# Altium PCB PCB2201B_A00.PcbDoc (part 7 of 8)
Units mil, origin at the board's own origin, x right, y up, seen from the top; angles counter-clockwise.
Board outline 4523.63 x 2358.23 mil, 6 copper layers (Top Layer, Signal Layer 2, Signal Layer 3, Signal Layer 4, Signal Layer 5, Bottom Layer), stack 61.221 mil thick; 383 components, 308 nets, 1386 pads, 1147 vias.
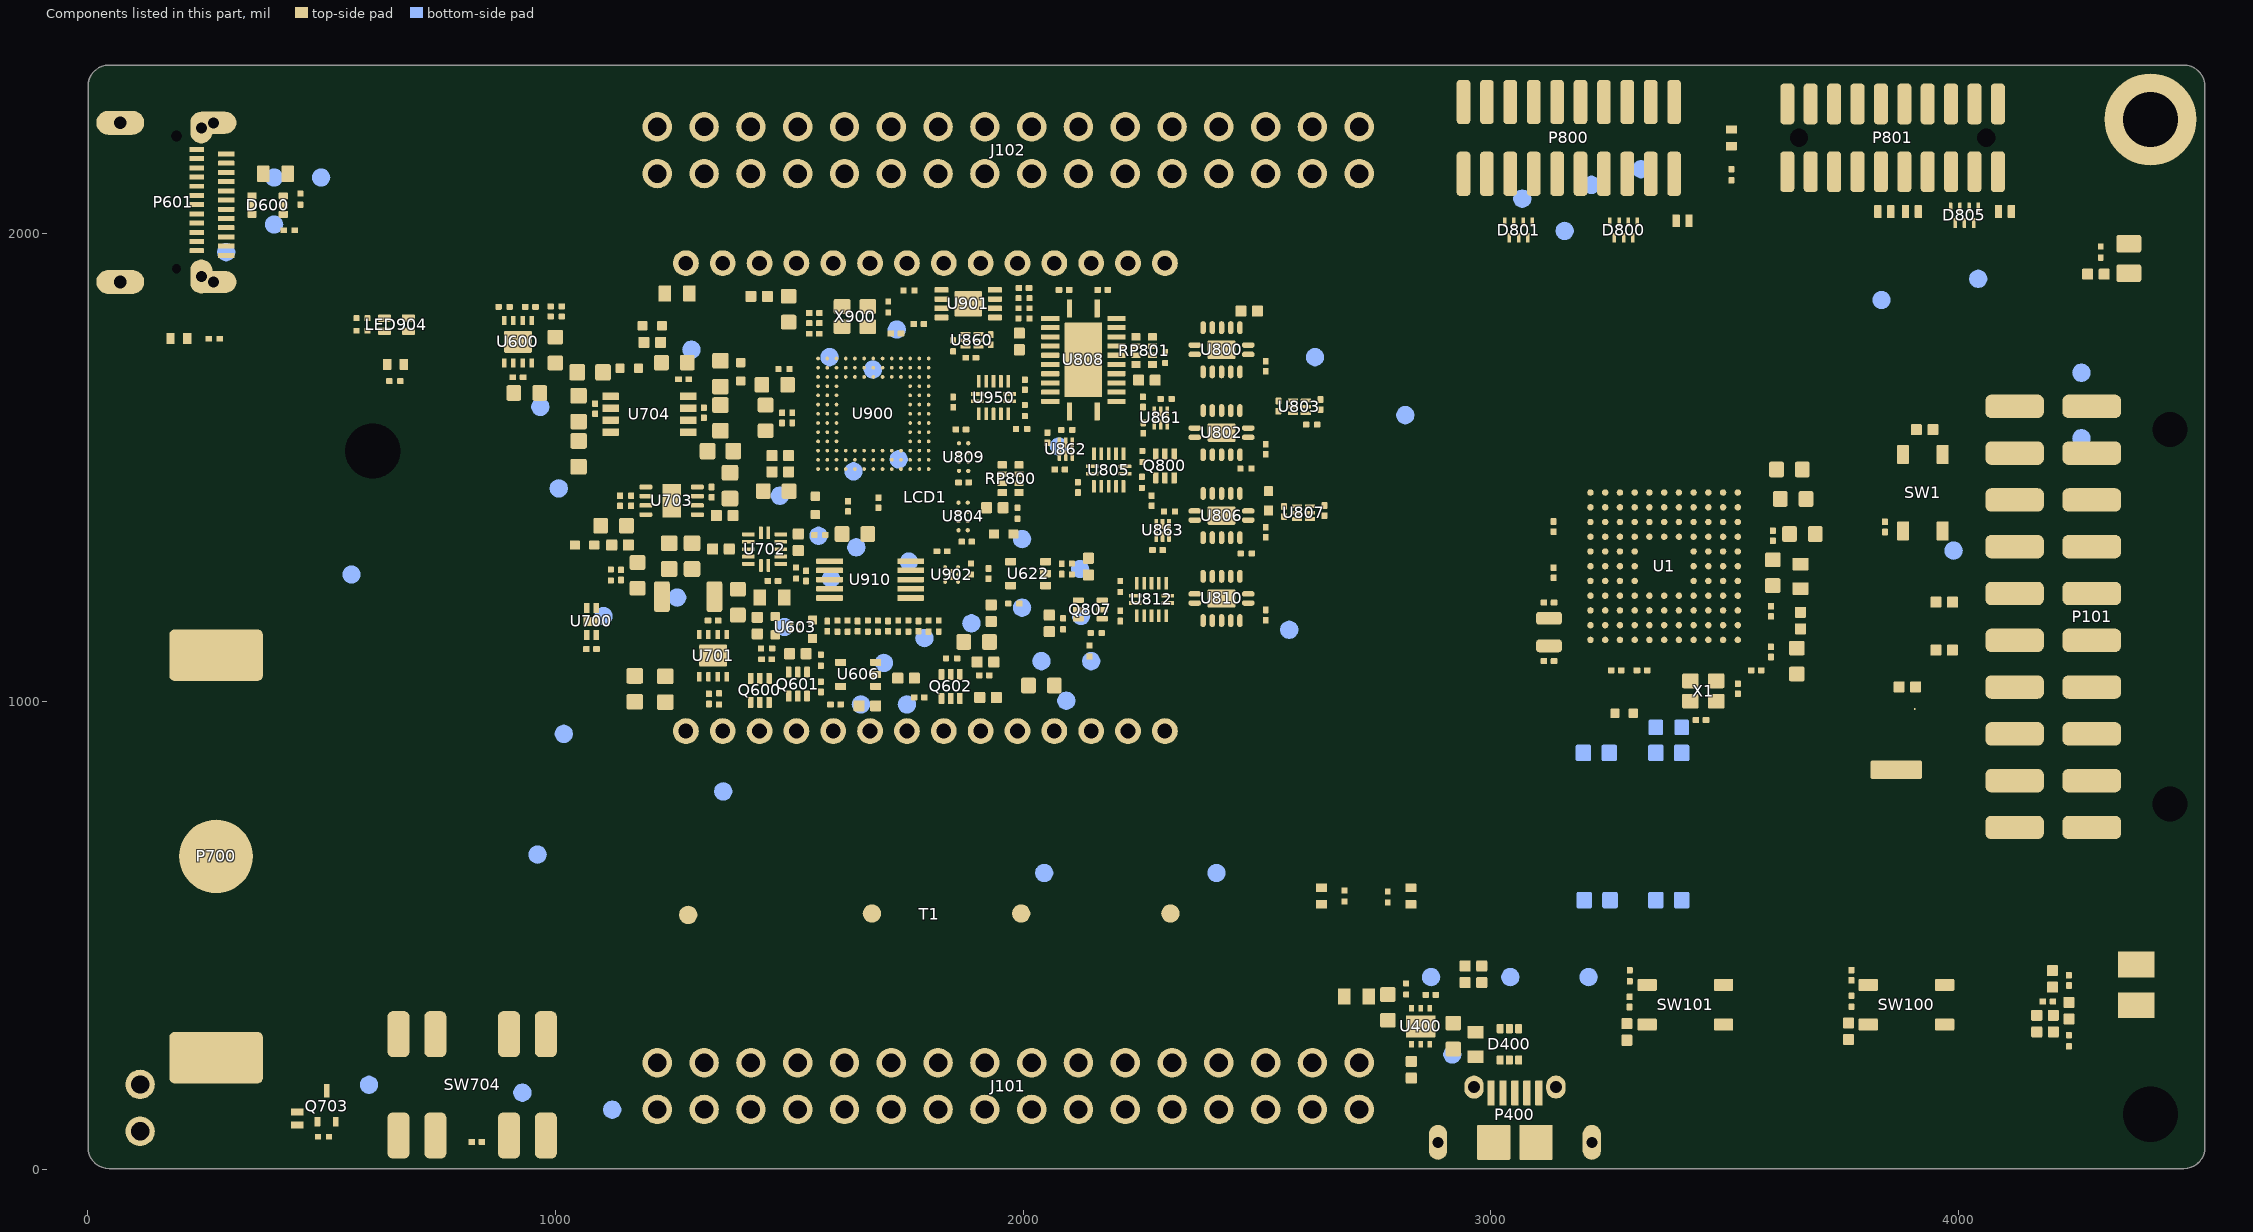
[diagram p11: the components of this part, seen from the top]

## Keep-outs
Bottom Layer:
  region: 2687,2128.47 ccw(c2718.5,2128.47) 2718.5,2096.98 ccw(c2718.5,2128.47) 2749.99,2128.47 ccw(c2718.5,2128.47) 2718.5,2159.97 ccw(c2718.5,2128.47)
  region: 2587,2128.47 ccw(c2618.5,2128.47) 2618.5,2096.98 ccw(c2618.5,2128.47) 2649.99,2128.47 ccw(c2618.5,2128.47) 2618.5,2159.97 ccw(c2618.5,2128.47)
  region: 1687,2128.47 ccw(c1718.5,2128.47) 1718.5,2096.98 ccw(c1718.5,2128.47) 1749.99,2128.47 ccw(c1718.5,2128.47) 1718.5,2159.97 ccw(c1718.5,2128.47)
  region: 1587,2128.47 ccw(c1618.5,2128.47) 1618.5,2096.98 ccw(c1618.5,2128.47) 1649.99,2128.47 ccw(c1618.5,2128.47) 1618.5,2159.97 ccw(c1618.5,2128.47)
  region: 1487,2128.47 ccw(c1518.5,2128.47) 1518.5,2096.98 ccw(c1518.5,2128.47) 1549.99,2128.47 ccw(c1518.5,2128.47) 1518.5,2159.97 ccw(c1518.5,2128.47)
  region: 1387,2128.47 ccw(c1418.5,2128.47) 1418.5,2096.98 ccw(c1418.5,2128.47) 1449.99,2128.47 ccw(c1418.5,2128.47) 1418.5,2159.97 ccw(c1418.5,2128.47)
  region: 1287,2128.47 ccw(c1318.5,2128.47) 1318.5,2096.98 ccw(c1318.5,2128.47) 1349.99,2128.47 ccw(c1318.5,2128.47) 1318.5,2159.97 ccw(c1318.5,2128.47)
  region: 2687,2228.47 ccw(c2718.5,2228.47) 2718.5,2196.98 ccw(c2718.5,2228.47) 2749.99,2228.47 ccw(c2718.5,2228.47) 2718.5,2259.97 ccw(c2718.5,2228.47)
  region: 2587,2228.47 ccw(c2618.5,2228.47) 2618.5,2196.98 ccw(c2618.5,2228.47) 2649.99,2228.47 ccw(c2618.5,2228.47) 2618.5,2259.97 ccw(c2618.5,2228.47)
  region: 2487,2228.47 ccw(c2518.5,2228.47) 2518.5,2196.98 ccw(c2518.5,2228.47) 2549.99,2228.47 ccw(c2518.5,2228.47) 2518.5,2259.97 ccw(c2518.5,2228.47)
  region: 2387,2228.47 ccw(c2418.5,2228.47) 2418.5,2196.98 ccw(c2418.5,2228.47) 2449.99,2228.47 ccw(c2418.5,2228.47) 2418.5,2259.97 ccw(c2418.5,2228.47)
  region: 2287,2228.47 ccw(c2318.5,2228.47) 2318.5,2196.98 ccw(c2318.5,2228.47) 2349.99,2228.47 ccw(c2318.5,2228.47) 2318.5,2259.97 ccw(c2318.5,2228.47)
  region: 2087,2228.47 ccw(c2118.5,2228.47) 2118.5,2196.98 ccw(c2118.5,2228.47) 2149.99,2228.47 ccw(c2118.5,2228.47) 2118.5,2259.97 ccw(c2118.5,2228.47)
  region: 1987,2228.47 ccw(c2018.5,2228.47) 2018.5,2196.98 ccw(c2018.5,2228.47) 2049.99,2228.47 ccw(c2018.5,2228.47) 2018.5,2259.97 ccw(c2018.5,2228.47)
  region: 1887,2228.47 ccw(c1918.5,2228.47) 1918.5,2196.98 ccw(c1918.5,2228.47) 1949.99,2228.47 ccw(c1918.5,2228.47) 1918.5,2259.97 ccw(c1918.5,2228.47)
  region: 1787,2228.47 ccw(c1818.5,2228.47) 1818.5,2196.98 ccw(c1818.5,2228.47) 1849.99,2228.47 ccw(c1818.5,2228.47) 1818.5,2259.97 ccw(c1818.5,2228.47)
  region: 1687,2228.47 ccw(c1718.5,2228.47) 1718.5,2196.98 ccw(c1718.5,2228.47) 1749.99,2228.47 ccw(c1718.5,2228.47) 1718.5,2259.97 ccw(c1718.5,2228.47)
  region: 1587,2228.47 ccw(c1618.5,2228.47) 1618.5,2196.98 ccw(c1618.5,2228.47) 1649.99,2228.47 ccw(c1618.5,2228.47) 1618.5,2259.97 ccw(c1618.5,2228.47)
  region: 1487,2228.47 ccw(c1518.5,2228.47) 1518.5,2196.98 ccw(c1518.5,2228.47) 1549.99,2228.47 ccw(c1518.5,2228.47) 1518.5,2259.97 ccw(c1518.5,2228.47)
  region: 1387,2228.47 ccw(c1418.5,2228.47) 1418.5,2196.98 ccw(c1418.5,2228.47) 1449.99,2228.47 ccw(c1418.5,2228.47) 1418.5,2259.97 ccw(c1418.5,2228.47)
  region: 1287,2228.47 ccw(c1318.5,2228.47) 1318.5,2196.98 ccw(c1318.5,2228.47) 1349.99,2228.47 ccw(c1318.5,2228.47) 1318.5,2259.97 ccw(c1318.5,2228.47)
  region: 2687,128.47 ccw(c2718.5,128.47) 2718.5,96.98 ccw(c2718.5,128.47) 2749.99,128.47 ccw(c2718.5,128.47) 2718.5,159.97 ccw(c2718.5,128.47)
  region: 2587,128.47 ccw(c2618.5,128.47) 2618.5,96.98 ccw(c2618.5,128.47) 2649.99,128.47 ccw(c2618.5,128.47) 2618.5,159.97 ccw(c2618.5,128.47)
  region: 2487,128.47 ccw(c2518.5,128.47) 2518.5,96.98 ccw(c2518.5,128.47) 2549.99,128.47 ccw(c2518.5,128.47) 2518.5,159.97 ccw(c2518.5,128.47)
  region: 2387,128.47 ccw(c2418.5,128.47) 2418.5,96.98 ccw(c2418.5,128.47) 2449.99,128.47 ccw(c2418.5,128.47) 2418.5,159.97 ccw(c2418.5,128.47)
  region: 2287,128.47 ccw(c2318.5,128.47) 2318.5,96.98 ccw(c2318.5,128.47) 2349.99,128.47 ccw(c2318.5,128.47) 2318.5,159.97 ccw(c2318.5,128.47)
  region: 2187,128.47 ccw(c2218.5,128.47) 2218.5,96.98 ccw(c2218.5,128.47) 2249.99,128.47 ccw(c2218.5,128.47) 2218.5,159.97 ccw(c2218.5,128.47)
  region: 2087,128.47 ccw(c2118.5,128.47) 2118.5,96.98 ccw(c2118.5,128.47) 2149.99,128.47 ccw(c2118.5,128.47) 2118.5,159.97 ccw(c2118.5,128.47)
  region: 1987,128.47 ccw(c2018.5,128.47) 2018.5,96.98 ccw(c2018.5,128.47) 2049.99,128.47 ccw(c2018.5,128.47) 2018.5,159.97 ccw(c2018.5,128.47)
  region: 1887,128.47 ccw(c1918.5,128.47) 1918.5,96.98 ccw(c1918.5,128.47) 1949.99,128.47 ccw(c1918.5,128.47) 1918.5,159.97 ccw(c1918.5,128.47)
  region: 1787,128.47 ccw(c1818.5,128.47) 1818.5,96.98 ccw(c1818.5,128.47) 1849.99,128.47 ccw(c1818.5,128.47) 1818.5,159.97 ccw(c1818.5,128.47)
  region: 1687,128.47 ccw(c1718.5,128.47) 1718.5,96.98 ccw(c1718.5,128.47) 1749.99,128.47 ccw(c1718.5,128.47) 1718.5,159.97 ccw(c1718.5,128.47)
  region: 1587,128.47 ccw(c1618.5,128.47) 1618.5,96.98 ccw(c1618.5,128.47) 1649.99,128.47 ccw(c1618.5,128.47) 1618.5,159.97 ccw(c1618.5,128.47)
  region: 1487,128.47 ccw(c1518.5,128.47) 1518.5,96.98 ccw(c1518.5,128.47) 1549.99,128.47 ccw(c1518.5,128.47) 1518.5,159.97 ccw(c1518.5,128.47)
  region: 1387,128.47 ccw(c1418.5,128.47) 1418.5,96.98 ccw(c1418.5,128.47) 1449.99,128.47 ccw(c1418.5,128.47) 1418.5,159.97 ccw(c1418.5,128.47)
  region: 1287,128.47 ccw(c1318.5,128.47) 1318.5,96.98 ccw(c1318.5,128.47) 1349.99,128.47 ccw(c1318.5,128.47) 1318.5,159.97 ccw(c1318.5,128.47)
  region: 1187,228.47 ccw(c1218.5,228.47) 1218.5,196.98 ccw(c1218.5,228.47) 1249.99,228.47 ccw(c1218.5,228.47) 1218.5,259.97 ccw(c1218.5,228.47)
  region: 2687,228.47 ccw(c2718.5,228.47) 2718.5,196.98 ccw(c2718.5,228.47) 2749.99,228.47 ccw(c2718.5,228.47) 2718.5,259.97 ccw(c2718.5,228.47)
  region: 2587,228.47 ccw(c2618.5,228.47) 2618.5,196.98 ccw(c2618.5,228.47) 2649.99,228.47 ccw(c2618.5,228.47) 2618.5,259.97 ccw(c2618.5,228.47)
  region: 2487,228.47 ccw(c2518.5,228.47) 2518.5,196.98 ccw(c2518.5,228.47) 2549.99,228.47 ccw(c2518.5,228.47) 2518.5,259.97 ccw(c2518.5,228.47)
  region: 2387,228.47 ccw(c2418.5,228.47) 2418.5,196.98 ccw(c2418.5,228.47) 2449.99,228.47 ccw(c2418.5,228.47) 2418.5,259.97 ccw(c2418.5,228.47)
  region: 2287,228.47 ccw(c2318.5,228.47) 2318.5,196.98 ccw(c2318.5,228.47) 2349.99,228.47 ccw(c2318.5,228.47) 2318.5,259.97 ccw(c2318.5,228.47)
  region: 2187,228.47 ccw(c2218.5,228.47) 2218.5,196.98 ccw(c2218.5,228.47) 2249.99,228.47 ccw(c2218.5,228.47) 2218.5,259.97 ccw(c2218.5,228.47)
  region: 2087,228.47 ccw(c2118.5,228.47) 2118.5,196.98 ccw(c2118.5,228.47) 2149.99,228.47 ccw(c2118.5,228.47) 2118.5,259.97 ccw(c2118.5,228.47)
  region: 1987,228.47 ccw(c2018.5,228.47) 2018.5,196.98 ccw(c2018.5,228.47) 2049.99,228.47 ccw(c2018.5,228.47) 2018.5,259.97 ccw(c2018.5,228.47)
  region: 1887,228.47 ccw(c1918.5,228.47) 1918.5,196.98 ccw(c1918.5,228.47) 1949.99,228.47 ccw(c1918.5,228.47) 1918.5,259.97 ccw(c1918.5,228.47)
  region: 1787,228.47 ccw(c1818.5,228.47) 1818.5,196.98 ccw(c1818.5,228.47) 1849.99,228.47 ccw(c1818.5,228.47) 1818.5,259.97 ccw(c1818.5,228.47)
  region: 1687,228.47 ccw(c1718.5,228.47) 1718.5,196.98 ccw(c1718.5,228.47) 1749.99,228.47 ccw(c1718.5,228.47) 1718.5,259.97 ccw(c1718.5,228.47)
  region: 1587,228.47 ccw(c1618.5,228.47) 1618.5,196.98 ccw(c1618.5,228.47) 1649.99,228.47 ccw(c1618.5,228.47) 1618.5,259.97 ccw(c1618.5,228.47)
  region: 1487,228.47 ccw(c1518.5,228.47) 1518.5,196.98 ccw(c1518.5,228.47) 1549.99,228.47 ccw(c1518.5,228.47) 1518.5,259.97 ccw(c1518.5,228.47)
  region: 1387,228.47 ccw(c1418.5,228.47) 1418.5,196.98 ccw(c1418.5,228.47) 1449.99,228.47 ccw(c1418.5,228.47) 1418.5,259.97 ccw(c1418.5,228.47)
  region: 1287,228.47 ccw(c1318.5,228.47) 1318.5,196.98 ccw(c1318.5,228.47) 1349.99,228.47 ccw(c1318.5,228.47) 1318.5,259.97 ccw(c1318.5,228.47)
  region: 4074.76,748.07 cw(c4074.76,728.38) 4094.45,728.39 cw(c4074.76,728.39) 4074.76,708.7 cw(c4074.76,728.38) 4055.08,728.38 cw(c4074.77,728.38)
  region: 4261.77,1582.7 cw(c4261.77,1563.01) 4281.46,1563.02 cw(c4261.77,1563.02) 4261.77,1543.33 cw(c4261.77,1563.01) 4242.09,1563.01 cw(c4261.78,1563.01)
  region: 4261.77,1722.4 cw(c4261.77,1702.71) 4281.46,1702.72 cw(c4261.77,1702.72) 4261.77,1683.03 cw(c4261.77,1702.71) 4242.09,1702.71 cw(c4261.78,1702.71)
  region: 4212.57,2133.9 cw(c4212.57,2114.21) 4232.26,2114.22 cw(c4212.57,2114.22) 4212.57,2094.53 cw(c4212.57,2114.21) 4192.89,2114.21 cw(c4212.58,2114.21)
  region: 4149.57,2066.9 cw(c4149.57,2047.21) 4169.26,2047.22 cw(c4149.57,2047.22) 4149.57,2027.53 cw(c4149.57,2047.21) 4129.89,2047.21 cw(c4149.58,2047.21)
  region: 4112.17,2133.9 cw(c4112.17,2114.21) 4131.86,2114.22 cw(c4112.17,2114.22) 4112.17,2094.53 cw(c4112.17,2114.21) 4092.49,2114.21 cw(c4112.18,2114.21)
  region: 4070.77,2066.9 cw(c4070.77,2047.21) 4090.46,2047.22 cw(c4070.77,2047.22) 4070.77,2027.53 cw(c4070.77,2047.21) 4051.09,2047.21 cw(c4070.78,2047.21)
  region: 4041.27,1923.2 cw(c4041.27,1903.51) 4060.96,1903.52 cw(c4041.27,1903.52) 4041.27,1883.83 cw(c4041.27,1903.51) 4021.59,1903.51 cw(c4041.28,1903.51)
  region: 3834.57,1878 cw(c3834.57,1858.31) 3854.26,1858.32 cw(c3834.57,1858.32) 3834.57,1838.63 cw(c3834.57,1858.31) 3814.89,1858.31 cw(c3834.58,1858.31)
  region: 3642.67,2064.3 cw(c3642.67,2044.61) 3662.36,2044.62 cw(c3642.67,2044.62) 3642.67,2024.93 cw(c3642.67,2044.61) 3622.99,2044.61 cw(c3642.68,2044.61)
  region: 3682.67,2134.3 cw(c3682.67,2114.61) 3702.36,2114.62 cw(c3682.67,2114.62) 3682.67,2094.93 cw(c3682.67,2114.61) 3662.99,2114.61 cw(c3682.68,2114.61)
  region: 3562.67,2064.3 cw(c3562.67,2044.61) 3582.36,2044.62 cw(c3562.67,2044.62) 3562.67,2024.93 cw(c3562.67,2044.61) 3542.99,2044.61 cw(c3562.68,2044.61)
  region: 3482.67,2064.3 cw(c3482.67,2044.61) 3502.36,2044.62 cw(c3482.67,2044.62) 3482.67,2024.93 cw(c3482.67,2044.61) 3462.99,2044.61 cw(c3482.68,2044.61)
  region: 3522.67,2134.3 cw(c3522.67,2114.61) 3542.36,2114.62 cw(c3522.67,2114.62) 3522.67,2094.93 cw(c3522.67,2114.61) 3502.99,2114.61 cw(c3522.68,2114.61)
  region: 3443.52,2134.15 cw(c3443.52,2114.46) 3463.21,2114.47 cw(c3443.52,2114.47) 3443.52,2094.78 cw(c3443.52,2114.46) 3423.84,2114.46 cw(c3443.53,2114.46)
  region: 3320.77,2157.5 cw(c3320.77,2137.81) 3340.46,2137.82 cw(c3320.77,2137.82) 3320.77,2118.13 cw(c3320.77,2137.81) 3301.09,2137.81 cw(c3320.78,2137.81)
  region: 3362.17,2055.1 cw(c3362.17,2035.41) 3381.86,2035.42 cw(c3362.17,2035.42) 3362.17,2015.73 cw(c3362.17,2035.41) 3342.49,2035.41 cw(c3362.18,2035.41)
  region: 3679.07,1685 cw(c3679.07,1665.31) 3698.76,1665.32 cw(c3679.07,1665.32) 3679.07,1645.63 cw(c3679.07,1665.31) 3659.39,1665.31 cw(c3679.08,1665.31)
  region: 3391.67,1576.8 cw(c3391.67,1557.11) 3411.36,1557.12 cw(c3391.67,1557.12) 3391.67,1537.43 cw(c3391.67,1557.11) 3371.99,1557.11 cw(c3391.68,1557.11)
  region: 3214.47,2124 cw(c3214.47,2104.31) 3234.16,2104.32 cw(c3214.47,2104.32) 3214.47,2084.63 cw(c3214.47,2104.31) 3194.79,2104.31 cw(c3214.48,2104.31)
  region: 3066.87,2094.5 cw(c3066.87,2074.81) 3086.56,2074.82 cw(c3066.87,2074.82) 3066.87,2055.13 cw(c3066.87,2074.81) 3047.19,2074.81 cw(c3066.88,2074.81)
  region: 3157.47,2025.6 cw(c3157.47,2005.91) 3177.16,2005.92 cw(c3157.47,2005.92) 3157.47,1986.23 cw(c3157.47,2005.91) 3137.79,2005.91 cw(c3157.48,2005.91)
  region: 3047.17,1909.4 cw(c3047.17,1889.71) 3066.86,1889.72 cw(c3047.17,1889.72) 3047.17,1870.03 cw(c3047.17,1889.71) 3027.49,1889.71 cw(c3047.18,1889.71)
  region: 2968.47,1909.4 cw(c2968.47,1889.71) 2988.16,1889.72 cw(c2968.47,1889.72) 2968.47,1870.03 cw(c2968.47,1889.71) 2948.79,1889.71 cw(c2968.48,1889.71)
  region: 2889.67,1909.4 cw(c2889.67,1889.71) 2909.36,1889.72 cw(c2889.67,1889.72) 2889.67,1870.03 cw(c2889.67,1889.71) 2869.99,1889.71 cw(c2889.68,1889.71)
  region: 3047.17,1822.8 cw(c3047.17,1803.11) 3066.86,1803.12 cw(c3047.17,1803.12) 3047.17,1783.43 cw(c3047.17,1803.11) 3027.49,1803.11 cw(c3047.18,1803.11)
  region: 2968.47,1822.8 cw(c2968.47,1803.11) 2988.16,1803.12 cw(c2968.47,1803.12) 2968.47,1783.43 cw(c2968.47,1803.11) 2948.79,1803.11 cw(c2968.48,1803.11)
  region: 2889.67,1822.8 cw(c2889.67,1803.11) 2909.36,1803.12 cw(c2889.67,1803.12) 2889.67,1783.43 cw(c2889.67,1803.11) 2869.99,1803.11 cw(c2889.68,1803.11)
  region: 2810.97,1822.8 cw(c2810.97,1803.11) 2830.66,1803.12 cw(c2810.97,1803.12) 2810.97,1783.43 cw(c2810.97,1803.11) 2791.29,1803.11 cw(c2810.98,1803.11)
  region: 2889.67,1716.5 cw(c2889.67,1696.81) 2909.36,1696.82 cw(c2889.67,1696.82) 2889.67,1677.13 cw(c2889.67,1696.81) 2869.99,1696.81 cw(c2889.68,1696.81)
  region: 2816.87,1631.9 cw(c2816.87,1612.21) 2836.56,1612.22 cw(c2816.87,1612.22) 2816.87,1592.53 cw(c2816.87,1612.21) 2797.19,1612.21 cw(c2816.88,1612.21)
  region: 2623.97,1755.9 cw(c2623.97,1736.21) 2643.66,1736.22 cw(c2623.97,1736.22) 2623.97,1716.53 cw(c2623.97,1736.21) 2604.29,1736.21 cw(c2623.98,1736.21)
  region: 3708.57,486.2 cw(c3708.57,466.51) 3728.26,466.52 cw(c3708.57,466.52) 3708.57,446.83 cw(c3708.57,466.51) 3688.89,466.51 cw(c3708.58,466.51)
  region: 3810.97,464.6 cw(c3810.97,444.91) 3830.66,444.92 cw(c3810.97,444.92) 3810.97,425.23 cw(c3810.97,444.91) 3791.29,444.91 cw(c3810.98,444.91)
  region: 3671.17,391.7 cw(c3671.17,372.01) 3690.86,372.02 cw(c3671.17,372.02) 3671.17,352.33 cw(c3671.17,372.01) 3651.49,372.01 cw(c3671.18,372.01)
  region: 3799.17,360.2 cw(c3799.17,340.51) 3818.86,340.52 cw(c3799.17,340.52) 3799.17,320.83 cw(c3799.17,340.51) 3779.49,340.51 cw(c3799.18,340.51)
  region: 3767.67,257.9 cw(c3767.67,238.21) 3787.36,238.22 cw(c3767.67,238.22) 3767.67,218.53 cw(c3767.67,238.21) 3747.99,238.21 cw(c3767.68,238.21)
  region: 3671.17,291.3 cw(c3671.17,271.61) 3690.86,271.62 cw(c3671.17,271.62) 3671.17,251.93 cw(c3671.17,271.61) 3651.49,271.61 cw(c3671.18,271.61)
  region: 3208.57,431.1 cw(c3208.57,411.41) 3228.26,411.42 cw(c3208.57,411.42) 3208.57,391.73 cw(c3208.57,411.41) 3188.89,411.41 cw(c3208.58,411.41)
  region: 3041.27,431.1 cw(c3041.27,411.41) 3060.96,411.42 cw(c3041.27,411.42) 3041.27,391.73 cw(c3041.27,411.41) 3021.59,411.41 cw(c3041.28,411.41)
  region: 2871.97,431.1 cw(c2871.97,411.41) 2891.66,411.42 cw(c2871.97,411.42) 2871.97,391.73 cw(c2871.97,411.41) 2852.29,411.41 cw(c2871.98,411.41)
  region: 2917.27,265.7 cw(c2917.27,246.01) 2936.96,246.02 cw(c2917.27,246.02) 2917.27,226.33 cw(c2917.27,246.01) 2897.59,246.01 cw(c2917.28,246.01)
  region: 2152.47,1638.8 cw(c2152.47,1619.11) 2172.16,1619.12 cw(c2152.47,1619.12) 2152.47,1599.43 cw(c2152.47,1619.11) 2132.79,1619.11 cw(c2152.48,1619.11)
  region: 2076.67,1565 cw(c2076.67,1545.31) 2096.36,1545.32 cw(c2076.67,1545.32) 2076.67,1525.63 cw(c2076.67,1545.31) 2056.99,1545.31 cw(c2076.68,1545.31)
  region: 1997.97,1367.1 cw(c1997.97,1347.41) 2017.66,1347.42 cw(c1997.97,1347.42) 1997.97,1327.73 cw(c1997.97,1347.41) 1978.29,1347.41 cw(c1997.98,1347.41)
  region: 2121.97,1303.1 cw(c2121.97,1283.41) 2141.66,1283.42 cw(c2121.97,1283.42) 2121.97,1263.73 cw(c2121.97,1283.41) 2102.29,1283.41 cw(c2121.98,1283.41)
  region: 1997.97,1220.5 cw(c1997.97,1200.81) 2017.66,1200.82 cw(c1997.97,1200.82) 1997.97,1181.13 cw(c1997.97,1200.81) 1978.29,1200.81 cw(c1997.98,1200.81)
  region: 2123.97,1202.8 cw(c2123.97,1183.11) 2143.66,1183.12 cw(c2123.97,1183.12) 2123.97,1163.43 cw(c2123.97,1183.11) 2104.29,1183.11 cw(c2123.98,1183.11)
  region: 2145.57,1106.3 cw(c2145.57,1086.61) 2165.26,1086.62 cw(c2145.57,1086.62) 2145.57,1066.93 cw(c2145.57,1086.61) 2125.89,1086.61 cw(c2145.58,1086.61)
  region: 2039.27,1106.3 cw(c2039.27,1086.61) 2058.96,1086.62 cw(c2039.27,1086.62) 2039.27,1066.93 cw(c2039.27,1086.61) 2019.59,1086.61 cw(c2039.28,1086.61)
  region: 2092.47,1021.7 cw(c2092.47,1002.01) 2112.16,1002.02 cw(c2092.47,1002.02) 2092.47,982.33 cw(c2092.47,1002.01) 2072.79,1002.01 cw(c2092.48,1002.01)
  region: 1889.67,1187 cw(c1889.67,1167.31) 1909.36,1167.32 cw(c1889.67,1167.32) 1889.67,1147.63 cw(c1889.67,1167.31) 1869.99,1167.31 cw(c1889.68,1167.31)
  region: 1789.27,1155.5 cw(c1789.27,1135.81) 1808.96,1135.82 cw(c1789.27,1135.82) 1789.27,1116.13 cw(c1789.27,1135.81) 1769.59,1135.81 cw(c1789.28,1135.81)
  region: 1850.37,1013.8 cw(c1850.37,994.11) 1870.06,994.12 cw(c1850.37,994.12) 1850.37,974.43 cw(c1850.37,994.11) 1830.69,994.11 cw(c1850.38,994.11)
  region: 1702.67,1102.4 cw(c1702.67,1082.71) 1722.36,1082.72 cw(c1702.67,1082.72) 1702.67,1063.03 cw(c1702.67,1082.71) 1682.99,1082.71 cw(c1702.68,1082.71)
  region: 1751.87,1013.8 cw(c1751.87,994.11) 1771.56,994.12 cw(c1751.87,994.12) 1751.87,974.43 cw(c1751.87,994.11) 1732.19,994.11 cw(c1751.88,994.11)
  region: 1653.47,1013.8 cw(c1653.47,994.11) 1673.16,994.12 cw(c1653.47,994.12) 1653.47,974.43 cw(c1653.47,994.11) 1633.79,994.11 cw(c1653.48,994.11)
  region: 2413.37,653.5 cw(c2413.37,633.81) 2433.06,633.82 cw(c2413.37,633.82) 2413.37,614.13 cw(c2413.37,633.81) 2393.69,633.81 cw(c2413.38,633.81)
  region: 2045.27,653.5 cw(c2045.27,633.81) 2064.96,633.82 cw(c2045.27,633.82) 2045.27,614.13 cw(c2045.27,633.81) 2025.59,633.81 cw(c2045.28,633.81)
  region: 1359.17,827.8 cw(c1359.17,808.11) 1378.86,808.12 cw(c1359.17,808.12) 1359.17,788.43 cw(c1359.17,808.11) 1339.49,808.11 cw(c1359.18,808.11)
  region: 962.57,692.9 cw(c962.57,673.21) 982.26,673.22 cw(c962.57,673.22) 962.57,653.53 cw(c962.57,673.21) 942.89,673.21 cw(c962.58,673.21)
  region: 616.07,1041.3 cw(c616.07,1021.61) 635.76,1021.62 cw(c616.07,1021.62) 616.07,1001.93 cw(c616.07,1021.61) 596.39,1021.61 cw(c616.08,1021.61)
  region: 474.37,1041.3 cw(c474.37,1021.61) 494.06,1021.62 cw(c474.37,1021.62) 474.37,1001.93 cw(c474.37,1021.61) 454.69,1021.61 cw(c474.38,1021.61)
  region: 473.37,1172.2 cw(c473.37,1152.51) 493.06,1152.52 cw(c473.37,1152.52) 473.37,1132.83 cw(c473.37,1152.51) 453.69,1152.51 cw(c473.38,1152.51)
  region: 372.97,1173.2 cw(c372.97,1153.51) 392.66,1153.52 cw(c372.97,1153.52) 372.97,1133.83 cw(c372.97,1153.51) 353.29,1153.51 cw(c372.98,1153.51)
  region: 564.87,1291.3 cw(c564.87,1271.61) 584.56,1271.62 cw(c564.87,1271.62) 564.87,1251.93 cw(c564.87,1271.61) 545.19,1271.61 cw(c564.88,1271.61)
  region: 409.37,1269.7 cw(c409.37,1250.01) 429.06,1250.02 cw(c409.37,1250.02) 409.37,1230.33 cw(c409.37,1250.01) 389.69,1250.01 cw(c409.38,1250.01)
  region: 409.37,1374 cw(c409.37,1354.31) 429.06,1354.32 cw(c409.37,1354.32) 409.37,1334.63 cw(c409.37,1354.31) 389.69,1354.31 cw(c409.38,1354.31)
  region: 726.17,1930.9 cw(c726.17,1911.21) 745.86,1911.22 cw(c726.17,1911.22) 726.17,1891.53 cw(c726.17,1911.21) 706.49,1911.21 cw(c726.18,1911.21)
  region: 626.17,1980.9 cw(c626.17,1961.21) 645.86,1961.22 cw(c626.17,1961.22) 626.17,1941.53 cw(c626.17,1961.21) 606.49,1961.21 cw(c626.18,1961.21)
  region: 726.17,2030.9 cw(c726.17,2011.21) 745.86,2011.22 cw(c726.17,2011.22) 726.17,1991.53 cw(c726.17,2011.21) 706.49,2011.21 cw(c726.18,2011.21)
  region: 626.17,2080.9 cw(c626.17,2061.21) 645.86,2061.22 cw(c626.17,2061.22) 626.17,2041.53 cw(c626.17,2061.21) 606.49,2061.21 cw(c626.18,2061.21)
  region: 726.17,2130.9 cw(c726.17,2111.21) 745.86,2111.22 cw(c726.17,2111.22) 726.17,2091.53 cw(c726.17,2111.21) 706.49,2111.21 cw(c726.18,2111.21)
  region: 626.17,2180.9 cw(c626.17,2161.21) 645.86,2161.22 cw(c626.17,2161.22) 626.17,2141.53 cw(c626.17,2161.21) 606.49,2161.21 cw(c626.18,2161.21)
  region: 499.97,2139.8 cw(c499.97,2120.11) 519.66,2120.12 cw(c499.97,2120.12) 499.97,2100.43 cw(c499.97,2120.11) 480.29,2120.11 cw(c499.98,2120.11)
  region: 399.57,2139.8 cw(c399.57,2120.11) 419.26,2120.12 cw(c399.57,2120.12) 399.57,2100.43 cw(c399.57,2120.11) 379.89,2120.11 cw(c399.58,2120.11)
  region: 399.57,2039.4 cw(c399.57,2019.71) 419.26,2019.72 cw(c399.57,2019.72) 399.57,2000.03 cw(c399.57,2019.71) 379.89,2019.71 cw(c399.58,2019.71)
  region: 297.17,1980.3 cw(c297.17,1960.61) 316.86,1960.62 cw(c297.17,1960.62) 297.17,1940.93 cw(c297.17,1960.61) 277.49,1960.61 cw(c297.18,1960.61)
  region: 968.47,1649.6 cw(c968.47,1629.91) 988.16,1629.92 cw(c968.47,1629.92) 968.47,1610.23 cw(c968.47,1629.91) 948.79,1629.91 cw(c968.48,1629.91)
  region: 1427.07,1478.3 cw(c1427.07,1458.61) 1446.76,1458.62 cw(c1427.07,1458.62) 1427.07,1438.93 cw(c1427.07,1458.61) 1407.39,1458.61 cw(c1427.08,1458.61)
  region: 1534.41,1478.13 cw(c1534.41,1458.44) 1554.1,1458.44 cw(c1534.4,1458.45) 1534.41,1438.76 cw(c1534.41,1458.44) 1514.72,1458.44 cw(c1534.41,1458.44)
  region: 1637.77,1511.8 cw(c1637.77,1492.11) 1657.46,1492.12 cw(c1637.77,1492.12) 1637.77,1472.43 cw(c1637.77,1492.11) 1618.09,1492.11 cw(c1637.78,1492.11)
  region: 1734.17,1537.4 cw(c1734.17,1517.71) 1753.86,1517.72 cw(c1734.17,1517.72) 1734.17,1498.03 cw(c1734.17,1517.71) 1714.49,1517.71 cw(c1734.18,1517.71)
  region: 1679.07,1729.3 cw(c1679.07,1709.61) 1698.76,1709.62 cw(c1679.07,1709.62) 1679.07,1689.93 cw(c1679.07,1709.61) 1659.39,1709.61 cw(c1679.08,1709.61)
  region: 1730.27,1815 cw(c1730.27,1795.31) 1749.96,1795.32 cw(c1730.27,1795.32) 1730.27,1775.63 cw(c1730.27,1795.31) 1710.59,1795.31 cw(c1730.28,1795.31)
  region: 726.17,1830.9 cw(c726.17,1811.21) 745.86,1811.22 cw(c726.17,1811.22) 726.17,1791.53 cw(c726.17,1811.21) 706.49,1811.21 cw(c726.18,1811.21)

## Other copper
Top Layer:
  region net N17454530: 136.13,304.15 136.13,218.2 177.15,177.18 414.87,177.18 414.87,304.15
  region net N17454530: 415.05,1034.44 415.05,1161.41 136.31,1161.41 136.31,1034.44
  pour cut-out: 1057.38,1345.64 1057.38,1323.32 1069.29,1323.32 1069.54,1323.57 1069.54,1345.64 1057.38,1345.64
  pour cut-out: 2000.83,1433.47 1998.06,1430.7 1998.06,1417.1 1996.55,1417.1 1986.73,1426.92 1992.77,1432.96 1992.77,1437.24
  pour cut-out: 3207.42,2176.71 3371.4,2176.71 3383.86,2164.25 3375.26,2155.65 3375.26,2079.19 3214.16,2079.19 3210.12,2083.23 3210.12,2172.68
  pour cut-out: 2957.42,2176.71 3112.81,2176.71 3122.56,2166.97 3122.56,2083.23 2960.12,2083.23 2957.42,2085.93
  pour cut-out: 1173.39,1388.85 1172.97,1388.43 1172.97,1323.17 1218.29,1323.17 1220.93,1325.81 1213.09,1333.65 1213.09,1357.78 1204.47,1357.78
  pour cut-out: 2028.54,1012.8 2031.13,1010.21 2031.13,994.31 2061.44,994.31 2062.99,992.76 2062.99,1012.54 2032.35,1012.54 2032.1,1012.8
  pour cut-out: 2361.15,1138.43 2361.15,1139.16 2369.78,1147.79 2379.28,1138.29 2406,1138.29 2406,1132.21 2394.99,1121.2 2368.86,1121.2 2368.86,1130.72
  pour cut-out: 2450.36,1189.8 2469.3,1189.8 2474.62,1184.49 2474.62,1172.12 2481.47,1172.12 2484.6,1168.98 2484.6,1199.59 2463.93,1199.59 2458.8,1204.72 2449.81,1195.73
  pour cut-out: 2559.52,1459.6 2557.66,1457.73 2557.66,1417.14 2504.76,1417.14 2493.58,1428.32 2493.58,1443.24 2509.94,1459.6
  pour cut-out: 2398.06,1428.31 2398.06,1422.93 2398.62,1422.38 2388.94,1412.7 2384.31,1412.7 2374.64,1422.36 2374.64,1432.78 2390.77,1432.78 2394.69,1428.87
  pour cut-out: 2355.23,1451.06 2356.92,1452.76 2373.8,1452.76 2373.8,1480.66 2370.28,1484.19 2347.86,1484.19 2347.86,1457.67 2348.41,1457.12
  pour cut-out: 1545.05,1086.51 1534.06,1075.52 1534.06,1031.2 1533.8,1030.95 1539.68,1025.07 1558.09,1025.07 1558.09,1084.46 1555.19,1087.36 1549.83,1087.36 1549.42,1086.96 1549.42,1083.36
  pour cut-out: 1774.66,1033.32 1775.43,1032.55 1775.43,1017.01 1812.26,1017.01 1816.06,1020.81 1815.48,1021.39 1815.48,1028 1798.14,1028 1793.98,1032.17
  pour cut-out: 2884.33,300.08 2884.33,278.82 2886.86,276.28 2901.62,276.28 2901.62,299.94 2901.11,300.44 2888.26,300.44 2886.5,302.2
  pour cut-out: 3949.72,2177.18 4016.81,2177.18 4016.81,2093.94 4013.44,2090.56 4013.09,2090.91 3941.22,2090.91 3941.22,2175.53 3945.61,2179.93 3952.47,2173.07
  pour cut-out: 3999.72,2322.18 4066.41,2322.18 4068.89,2319.7 4066.28,2317.08 4066.28,2227.99 4001.34,2227.99 3997.5,2231.84 3998.11,2232.46 3998.11,2321.24
  pour cut-out: 3666.81,2322.18 3668.35,2320.64 3668.35,2227.6 3651.17,2227.6 3647.37,2231.4 3647.37,2320.03
  pour cut-out: 1946.85,1514.76 1946.85,1438.98 2001.97,1438.98 2001.97,1514.76
  pour cut-out: 2231.3,1787.4 2231.3,1711.61 2286.42,1711.61 2286.42,1787.4
  region net 3V3: 4019.61,1578.74 4188.9,1578.74 4188.9,1696.85 4019.61,1696.85
  pour cut-out: 3096.46,1191.93 3096.46,1105.32 3151.57,1105.32 3151.57,1191.93
  region net BC_I2C_EXP_SDA: 4378.2,1578.74 4208.91,1578.74 4208.91,1696.85 4378.2,1696.85
  region net GND: 4378.2,783.46 4208.91,783.46 4208.91,665.35 4378.2,665.35
  region net VMCU: 4019.61,783.46 4188.9,783.46 4188.9,665.35 4019.61,665.35
  pour cut-out: 1208.66,370.08 1208.66,724.41 2389.76,724.41 2389.76,370.08
  pour cut-out: 4265.75,286.42 4265.75,504.92 4478.35,504.92 4478.35,286.42
Signal Layer 2:
  pour cut-out: 1208.66,370.08 1208.66,724.41 2389.76,724.41 2389.76,370.08
  pour cut-out: 4265.75,286.42 4265.75,504.92 4478.35,504.92 4478.35,286.42
Signal Layer 3:
  pour cut-out: 3472.8,918.43 3471.27,916.9 3471.27,896.47 3465.49,896.47 3461.2,900.77 3464.29,903.86 3464.29,916.3
  pour cut-out: 3170.2,872.36 3169.13,871.3 3169.13,852.87 3183.31,852.87 3182.6,853.58 3182.6,875.91 3174.09,875.91 3172.68,874.49
  pour cut-out: 3219.09,784.13 3219.8,783.43 3219.8,755.08 3228.31,755.08 3229.37,756.14 3222.99,762.52 3222.99,788.39 3222.28,788.39 3221.22,787.32
  pour cut-out: 1802.13,830.55 1801.42,829.84 1801.42,796.54 1815.59,796.54 1809.57,802.56 1809.57,836.93 1799.29,836.93 1800.35,835.87 1801.06,835.87 1801.06,831.61
  pour cut-out: 1313.94,1958.3 1520.57,1958.3 1544.06,1981.79 1324.31,1981.79 1318.9,1976.38
  pour cut-out: 1555.78,2081.21 1555.78,2033.94 1558.35,2031.38 1558.7,2031.73 1563.31,2031.73 1563.31,2083.62 1560.75,2086.18
  pour cut-out: 2802.05,1426.54 2802.05,1320.35 2803.64,1318.76 2802.24,1317.36 2798.2,1317.36 2798.2,1424.36 2798.15,1424.41
  pour cut-out: 2837.48,1547.36 2837.48,1441.18 2839.07,1439.58 2837.67,1438.18 2833.63,1438.18 2833.63,1545.19 2833.58,1545.24
  pour cut-out: 3184.37,1475.08 3184.37,1368.89 3185.96,1367.3 3180.47,1302.13 3180.52,1365.9 3180.52,1472.91 3180.47,1472.95
  pour cut-out: 3518.72,1624.77 3518.72,1518.58 3520.31,1516.99 3518.91,1515.59 3514.87,1515.59 3514.87,1622.59 3514.82,1622.64
  pour cut-out: 3523.46,1627.09 2987.72,1320.24 3005.79,1562.6
  pour cut-out: 2474.65,959.53 2475.35,958.82 2475.35,902.48 2485.28,902.48 2482.8,904.96 2482.8,959.17
  pour cut-out: 2969.65,1002.05 2969.65,895.86 2971.24,894.27 2969.84,892.87 2965.8,892.87 2965.8,999.87 2965.75,999.92
  pour cut-out: 2469.68,1067.24 2469.68,1050.14 2463.34,1043.8 2452.94,1043.8 2452.94,1065.91 2451.61,1067.24
  pour cut-out: 2125.98,1046.34 2120.78,1041.14 2120.78,1029.74 2131.95,1029.74 2132.01,1029.69 2132.01,1044.92
  pour cut-out: 2814.47,653.11 2814.47,618.68 2804.17,608.39 2791.06,608.39 2791.06,640.28 2788.58,642.76
  pour cut-out: 2786.1,695.91 2778.28,688.08 2778.28,680.25 2769.74,680.25 2767.32,677.83 2767.32,696.26
  pour cut-out: 1601.93,104.53 1598.38,108.07 1548.79,108.07 1548.79,93.91 1551.5,96.61 1600.14,96.61
  pour cut-out: 3472.81,1132.54 3468.19,1127.92 3456.82,1127.92 3529.9,1054.84 3562.44,1054.84 3562.44,1076.46 3562.8,1076.81 3562.09,1077.52 3519.57,1077.52 3519.57,1085.78
  pour cut-out: 2126.74,1524.96 2128.53,1523.16 2128.53,1502.12 2191.02,1502.12 2200.64,1511.74 2191.02,1521.37 2191.02,1566.07 2184.16,1566.07 2172.74,1554.65 2160.35,1554.65
  pour cut-out: 2349.8,1681.98 2349.8,1666.62 2345.91,1662.73 2363.8,1644.84 2363.8,1636.67 2371.19,1636.67 2382.47,1647.95 2382.47,1667.4 2377.41,1667.4 2360.5,1684.32
  pour cut-out: 2384.29,1605.12 2384.29,1587.74 2373.14,1576.58 2494.29,1576.58 2494.29,1585.34 2497.4,1588.45 2483.98,1601.87 2473.28,1601.87
  pour cut-out: 2826.35,1702.07 2826.35,1694.61 2829.58,1691.38 3410.07,1691.38 3410.07,1704.67 3410.08,1704.69 3409.8,1704.96 2827.45,1704.96
  pour cut-out: 2842.71,2056.42 2840.86,2054.57 2840.86,2042.02 2887.5,1995.37 2895.91,1995.37 2895.91,2012.51 2851.54,2056.89 2847.55,2056.89
  pour cut-out: 1208.66,370.08 1208.66,724.41 2389.76,724.41 2389.76,370.08
  pour cut-out: 4265.75,286.42 4265.75,504.92 4478.35,504.92 4478.35,286.42
Signal Layer 4:
  pour cut-out: 4270.75,2072.83 4286.16,2075.32 4287.22,2074.25 4296.26,2101.89 4272.7,2084.17
  pour cut-out: 4207,2094.41 4222.41,2096.89 4223.48,2095.82 4232.51,2123.46 4208.95,2105.74
  pour cut-out: 3640.75,1046.69 3656.16,1049.17 3657.22,1048.11 3666.26,1075.75 3642.7,1058.03
  pour cut-out: 3704.17,1036.06 3719.59,1038.54 3720.65,1037.48 3729.68,1065.12 3706.12,1047.4
  pour cut-out: 3433.82,875.91 3449.23,878.39 3450.3,877.32 3459.33,904.96 3435.77,887.24
  pour cut-out: 2648.98,612.28 2664.39,614.76 2665.45,613.7 2674.49,641.34 2650.93,623.62
  pour cut-out: 1948.49,137.93 1959.48,137.93 1983.02,114.38 1983.02,146.79 1946.01,146.79
  pour cut-out: 2076.28,128.43 2087.26,128.43 2088.33,127.36 2088.33,137.28 2073.8,137.28
  pour cut-out: 2511.4,1075.66 2527.67,1084.14 2528.73,1083.08 2528.73,1093 2514.21,1093
  pour cut-out: 1964.11,286.55 1975.1,286.55 1976.16,285.49 1976.16,297.28 1961.11,297.28
  pour cut-out: 1885.05,309.64 1896.03,309.64 1897.1,308.58 1897.1,319.96 1882.16,319.96
  pour cut-out: 2598.13,664.37 2609.11,664.37 2610.18,663.31 2610.18,673.23 2595.65,673.23
  pour cut-out: 2543.03,754.02 2558.44,756.5 2559.51,755.43 2568.54,783.07 2544.98,765.35
  pour cut-out: 3090.01,921.96 3100.99,921.96 3102.06,920.9 3102.06,930.82 3087.53,930.82
  pour cut-out: 3007.38,918.07 3018.37,918.07 3019.43,917.01 3019.43,926.93 3004.9,926.93
  pour cut-out: 2923.04,882.8 2940.48,882.8 2940.48,892.72 2920.26,892.72
  pour cut-out: 2944.31,806.46 2955.3,806.46 2956.36,805.39 2956.36,815.31 2941.83,815.31
  pour cut-out: 2903.92,705.12 2914.9,705.12 2932.09,687.93 2932.09,713.98 2901.44,713.98
  pour cut-out: 2808.62,1386.81 2819.6,1386.81 2874.68,1331.73 2874.68,1395.67 2806.14,1395.67
  pour cut-out: 2674.04,1410.85 2685.03,1410.85 2696.87,1399.01 2696.87,1419.71 2671.56,1419.71
  pour cut-out: 2499.99,1637.77 2510.97,1637.77 2512.03,1636.71 2512.03,1646.63 2497.51,1646.63
  pour cut-out: 2498.41,1726.65 2517.34,1726.65 2520.11,1723.89 2520.11,1735.51 2495.93,1735.51
  pour cut-out: 2640.65,1661.46 2651.63,1661.46 2654.4,1658.69 2654.4,1670.31 2638.17,1670.31
  pour cut-out: 3269.4,1210.63 3280.39,1210.63 3281.45,1209.57 3281.45,1219.49 3266.92,1219.49
  pour cut-out: 3187.15,246.19 3187.15,264.29 3195.68,272.82 3204.92,263.58 3204.92,259.65 3212.6,251.97 3208.09,247.46 3188.43,247.46
  pour cut-out: 3140.88,390.75 3142.02,391.89 3153.54,391.89 3153.54,396.5 3147.8,390.75 3140.88,390.75 3140.88,398.88 3140.43,399.33 3141.14,400.04 3156.73,400.04 3156.73,392.24 3157.09,391.89 3151.06,391.89
  pour cut-out: 3233.62,603.07 3244.61,603.07 3245.67,602.01 3245.67,611.93 3231.14,611.93
  pour cut-out: 3205.72,680.03 3208.12,682.44 3223.35,682.44 3223.35,691.65 3223.7,692.01 3218.74,696.97 3201.38,696.97
  pour cut-out: 1208.66,370.08 1208.66,724.41 2389.76,724.41 2389.76,370.08
  pour cut-out: 4265.75,286.42 4265.75,504.92 4478.35,504.92 4478.35,286.42
Signal Layer 5:
  pour cut-out: 1208.66,370.08 1208.66,724.41 2389.76,724.41 2389.76,370.08
  pour cut-out: 4265.75,286.42 4265.75,504.92 4478.35,504.92 4478.35,286.42
Bottom Layer:
  pour cut-out: 2709.69,1831.74 2712.02,1829.41 2742.87,1829.41 2744.65,1827.64 2741.1,1824.09 2741.1,1814.17 2724.35,1814.17 2711.75,1826.77
  pour cut-out: 2038.41,1571.22 2038.66,1570.97 2063.98,1570.97 2063.98,1566.49 2060.48,1562.98 2041.98,1562.98 2032.59,1572.38
  pour cut-out: 1933.75,1569.97 1934.56,1570.78 1971.18,1570.78 1971.18,1566.12 1970.02,1564.96 1965.01,1569.97 1933.75,1569.97 1933.75,1568.34 1937.05,1565.04
  pour cut-out: 1917.15,1259.34 1923.12,1265.32 1917.15,1259.34 1924.99,1251.5 1932.87,1251.5 1935.35,1253.98
  pour cut-out: 2028.73,1132.6 2028.73,1095.29 2024.88,1091.44 2013.99,1102.32 1996.65,1102.32 1996.65,1129.94 1999.31,1132.6
  pour cut-out: 2250.31,2110.06 2252.42,2112.17 2273.39,2112.17 2273.39,2100.63 2344.49,2029.53 2343.07,2028.11 2328.76,2028.11 2248.79,2108.07
  pour cut-out: 4265.65,286.42 4265.85,504.92 4478.25,504.92 4478.25,286.42

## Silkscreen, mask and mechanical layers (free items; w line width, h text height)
Top Overlay:
  lines w7.87: 3433.07,2205.71 3490.16,2205.71 ; 3537.4,2205.71 3594.49,2205.71
  text "5V" at 1188.19,2295.28 h47.24
  text "GND" at 1275,2295.28 h47.24
  text "D0" at 1394.68,2295.28 h47.24
  text "D1" at 1494.68,2295.28 h47.24
  text "D2" at 1594.68,2295.28 h47.24
  text "D3" at 1694.68,2295.28 h47.24
  text "D4" at 1794.68,2295.28 h47.24
  text "D5" at 1894.68,2295.28 h47.24
  text "D6" at 1994.68,2295.28 h47.24
  text "D7" at 2094.68,2295.28 h47.24
  text "D8" at 2196.06,2295.28 h47.24
  text "D13" at 2282.87,2295.28 h47.24
  text "D14" at 2382.87,2295.28 h47.24
  text "D15" at 2482.87,2295.28 h47.24
  text "GND" at 2575,2295.28 h47.24
  text "3V3" at 2686.81,2295.28 h47.24
  text "1" at 3444.88,2263.78 h59.06
  text "1" at 4122.05,2255.91 h59.06
  text "2" at 4118.11,2110.24 h59.06
  text "2" at 3437.01,2082.68 h59.06
  text "5V" at 1181.1,2031.5 h47.24
  text "GND" at 1267.91,2031.5 h47.24
  text "B9" at 1394.68,2031.5 h47.24
  text "B10" at 1482.87,2031.5 h47.24
  text "B11" at 1582.87,2031.5 h47.24
  text "NC" at 1690.75,2031.5 h47.24
  text "E8" at 1794.68,2031.5 h47.24
  text "E9" at 1894.68,2031.5 h47.24
  text "E10" at 1986.81,2031.5 h47.24
  text "E11" at 2086.81,2031.5 h47.24
  text "E12" at 2184.25,2031.5 h47.24
  text "E13" at 2286.81,2031.5 h47.24
  text "E14" at 2386.81,2031.5 h47.24
  text "E15" at 2486.81,2031.5 h47.24
  text "GND" at 2575,2031.5 h47.24
  text "3V3" at 2686.81,2031.5 h47.24
  text "SIMPLICITY" at 3606.38,1920.83 h62.99
  text "DEBUG" at 2906.14,1909.45 h62.99
  text "Light Sense" at 4133.86,1830.71 h78.74
  text "Leopard Gecko" at 2956.69,1649.61 h110.24
  text "RESET" at 3788.86,1264.96 h78.74
  text "EFM32LG990" at 3181.54,891.85 h78.74
  text "2" at 4114.17,645.67 h59.06
  text "1" at 4263.78,645.67 h59.06
  text "LC Sense" at 4178.98,524.76 h78.74
  text "LED1" at 2568.96,479.21 h78.74
  text "LED0" at 2757.87,479.21 h78.74
  text "BAT" at 618.11,354.33 h78.74
  text "USB" at 777.56,354.33 h78.74
  text "AEM" at 940.94,354.33 h78.74
  text "VMCU" at 1133.27,295.28 h47.24
  text "GND" at 1275,295.28 h47.24
  text "C0" at 1395.67,295.28 h47.24
  text "C1" at 1491.73,295.28 h47.24
  text "C2" at 1591.73,295.28 h47.24
  text "C3" at 1691.73,295.28 h47.24
  text "C4" at 1791.73,295.28 h47.24
  text "C5" at 1891.73,295.28 h47.24
  text "C6" at 1991.73,295.28 h47.24
  text "C7" at 2091.73,295.28 h47.24
  text "NC" at 2187.8,295.28 h47.24
  text "F0" at 2295.67,295.28 h47.24
  text "F1" at 2395.67,295.28 h47.24
  text "F2" at 2495.67,295.28 h47.24
  text "GND" at 2575,295.28 h47.24
  text "3V3" at 2686.81,295.28 h47.24
  text "BTN1" at 3326.77,196.85 h78.74
  text "BTN0" at 3799.21,196.85 h78.74
  text "VMCU" at 1133.27,31.5 h47.24
  text "GND" at 1275,31.5 h47.24
  text "A12" at 1382.87,31.5 h47.24
  text "A13" at 1482.87,31.5 h47.24
  text "A14" at 1582.87,31.5 h47.24
  text "B15" at 1694.68,31.5 h47.24
  text "E0" at 1798.62,31.5 h47.24
  text "E1" at 1898.62,31.5 h47.24
  text "E2" at 1998.62,31.5 h47.24
  text "E3" at 2094.68,31.5 h47.24
  text "NC" at 2194.68,31.5 h47.24
  text "NC" at 2294.68,31.5 h47.24
  text "F8" at 2398.62,31.5 h47.24
  text "F9" at 2498.62,31.5 h47.24
  text "GND" at 2578.94,31.5 h47.24
  text "3V3" at 2686.81,31.5 h47.24
Bottom Overlay:
  lines w5.98: 3181.18,508.46 3216.61,508.46 ; 3181.18,824.53 3216.61,824.53 ; 3187.91,814.61 3209.88,814.61 ; 3189.33,497.48 3211.3,497.48 ; 3195.35,803.98 3204.21,803.98 ; 3195.71,486.14 3204.57,486.14 ; 3198.9,824.17 3198.9,857.13 ; 3199.61,509.53 3199.61,542.48 ; 3280.39,574.49 3325.04,574.49 ; 3280.39,889.45 3325.04,889.45 ; 3307.68,574.91 3307.68,680.67 3345.59,680.67 ; 3308.39,889.4 3308.39,782.36 3346.3,782.36 ; 3345.94,823.82 3345.94,639.73 3507.52,732.05 ; 3346.65,823.82 3507.76,731.77 ; 3355.16,681.02 3376.77,681.02 ; 3355.51,782.72 3377.13,782.72 ; 3365.79,670.04 3365.79,691.65 ; 3433.82,889.45 3532.24,889.45 ; 3434.53,574.49 3532.95,574.84 ; 3507.4,731.98 3595.98,731.98 ; 3533.03,574.49 3533.03,889.45
  lines w6: 4019.66,803.12 4208.66,803.12 ; 4019.66,901.62 4204.76,901.62 ; 4019.66,1000.02 4208.66,1000.02 ; 4019.66,1098.42 4208.66,1098.42 ; 4019.66,1196.82 4208.66,1196.82 ; 4019.66,1295.32 4204.76,1295.32 ; 4019.66,1393.72 4208.66,1393.72 ; 4019.66,1492.12 4208.66,1492.12 ; 4019.66,1590.52 4208.66,1590.52 ; 4025.52,1689.02 4019.66,1689.02 ; 4072.86,901.62 4208.66,901.62 ; 4072.86,1295.32 4208.66,1295.32 ; 4114.16,704.72 4114.16,1689.02 ; 4114.16,1098.42 4204.76,1098.42 ; 4019.66,1689.02 4208.66,1689.02 4208.66,704.72 4019.66,704.72 4019.66,1689.02
  text "3V3" at 4323.54,1616.85 h66.93
  text "19" at 4096.77,1615.78 h66.93
  text "20" at 4190.02,1615.07 h66.93
  text "5V" at 4367.15,1529.31 h66.93
  text "18" at 4190.67,1517.99 h66.93
  text "17" at 4098.54,1517.24 h66.93
  text "I2C_SCL" at 3995.43,1420.35 h66.93
  text "15" at 4098.19,1420.19 h66.93
  text "16" at 4193.15,1419.84 h66.93
  text "I2C_SDA" at 4463.86,1419.64 h66.93
  text "13" at 4095.71,1323.11 h66.93
  text "14" at 4191.73,1321.3 h66.93
  text "UART_RX" at 4495.39,1315.82 h66.93
  text "12" at 4190.67,1219.96 h66.93
  text "11" at 4098.54,1219.25 h66.93
  text "UART_TX" at 4486.18,1217.32 h66.93
  text "10" at 4191.73,1125.39 h66.93
  text "SPI_CS" at 4424.53,1125.55 h66.93
  text "9" at 4084.72,1123.97 h66.93
  text "8" at 4175.43,1025.47 h66.93
  text "7" at 4078.35,1024.02 h66.93
  text "SPI_SCK" at 4468.11,1024.21 h66.93
  text "SPI_MISO" at 4493.98,930.31 h66.93
  text "5" at 4081.54,927.67 h66.93
  text "6" at 4179.33,926.25 h66.93
  text "3" at 4078.35,830.23 h66.93
  text "4" at 4172.24,829.13 h66.93
  text "SPI_MOSI" at 4493.62,825.78 h66.93
  text "2" at 4174.08,735.24 h66.93
  text "1" at 4075.87,733.46 h66.93
  text "VMCU" at 4388.32,733.14 h66.93
  text "GND" at 4001.81,730.66 h66.93
  text "BOARD INFO" at 779.53,618.11 h60
  text "BAT" at 291.34,161.42 h60
  text "GND" at 293.31,57.09 h60
  text "PCB2201B Rev A00" at 3960.63,47.24 h60
Top Solder:
  lines w31.5: 334.66,-94.51 47.26,-94.51 cw(c47.26,47.23) -94.47,47.23 -94.47,2314.94 cw(c47.26,2314.94) 47.26,2456.67 334.66,2456.67 ; 610.25,-94.51 2224.43,-94.51 ; 610.25,2456.67 2224.43,2456.67 ; 2500.02,-94.51 3720.49,-94.51 ; 2500.02,2456.67 3720.49,2456.67 ; 3996.08,-94.51 4480.33,-94.51 ccw(c4480.33,47.23) 4622.06,47.23 4622.06,2314.94 ccw(c4480.33,2314.94) 4480.33,2456.67 3996.08,2456.67 ; 0.02,47.23 ccw(c47.26,47.23) 47.26,-0.02 4480.33,-0.02 ccw(c4480.33,47.23) 4527.57,47.23 4527.57,2314.94 ccw(c4480.33,2314.94) 4480.33,2362.19 47.26,2362.19 ccw(c47.26,2314.94) 0.02,2314.94 0.02,47.23
Bottom Solder:
  lines w31.5: 334.66,-94.51 47.26,-94.51 cw(c47.26,47.23) -94.47,47.23 -94.47,2314.94 cw(c47.26,2314.94) 47.26,2456.67 334.66,2456.67 ; 610.25,-94.51 2224.43,-94.51 ; 610.25,2456.67 2224.43,2456.67 ; 2500.02,-94.51 3720.49,-94.51 ; 2500.02,2456.67 3720.49,2456.67 ; 3996.08,-94.51 4480.33,-94.51 ccw(c4480.33,47.23) 4622.06,47.23 4622.06,2314.94 ccw(c4480.33,2314.94) 4480.33,2456.67 3996.08,2456.67 ; 0.02,47.23 ccw(c47.26,47.23) 47.26,-0.02 4480.33,-0.02 ccw(c4480.33,47.23) 4527.57,47.23 4527.57,2314.94 ccw(c4480.33,2314.94) 4480.33,2362.19 47.26,2362.19 ccw(c47.26,2314.94) 0.02,2314.94 0.02,47.23
BOARD OUTLINE:
  circle w3.94: c610.24,1535.43 r59.06
  circle w3.94: c4409.45,2244.09 r59.06
  lines w3.94: -0.01,47.25 ccw(c47.23,47.25) 47.23,0.01 ; -0.01,47.25 ccw(c47.23,47.25) 47.23,0.01 ; -0.01,47.25 ccw(c47.23,47.25) 47.23,0.01 ; -0.01,47.25 ccw(c47.23,47.25) 47.23,0.01 ; -0.01,47.25 -0.01,2314.97 ; 0,47.25 0,2314.97 ; -0.01,47.25 -0.01,2314.97 ; -0.01,47.25 -0.01,2314.97 ; -0.01,2314.97 cw(c47.23,2314.97) 47.23,2362.21 ; -0.01,2314.97 cw(c47.23,2314.97) 47.23,2362.21 ; -0.01,2314.97 cw(c47.23,2314.97) 47.23,2362.21 ; -0.01,2314.97 cw(c47.23,2314.97) 47.23,2362.21 ; 47.23,0.01 4480.3,0.01 ; 47.23,0.01 4480.3,0.01 ; 47.23,0.01 4480.3,0.01 ; 47.23,0.01 4480.3,0.01 ; 47.23,2362.21 4480.3,2362.21 ; 47.23,2362.21 4480.3,2362.21 ; 47.23,2362.21 4480.3,2362.21 ; 47.23,2362.21 4480.3,2362.21 ; 4480.3,0.01 ccw(c4480.3,47.25) 4527.55,47.25 ; 4480.3,0.01 ccw(c4480.3,47.25) 4527.55,47.25 ; 4480.3,0.01 ccw(c4480.3,47.25) 4527.55,47.25 ; 4480.3,0.01 ccw(c4480.3,47.25) 4527.55,47.25 ; 4480.3,2362.21 cw(c4480.3,2314.97) 4527.55,2314.97 ; 4480.3,2362.21 cw(c4480.3,2314.97) 4527.55,2314.97 ; 4480.3,2362.21 cw(c4480.3,2314.97) 4527.55,2314.97 ; 4480.3,2362.21 cw(c4480.3,2314.97) 4527.55,2314.97 ; 4527.55,47.25 4527.55,2314.97 ; 4527.55,47.25 4527.55,2314.97 ; 4527.55,47.25 4527.55,2314.97 ; 4527.55,47.25 4527.55,2314.97
Route Tool Path:
  lines w3.94: -94.49,47.24 ccw(c47.24,47.24) 47.24,-94.49 ; -94.49,47.24 ccw(c47.24,47.24) 47.24,-94.49 ; -94.49,47.24 ccw(c47.24,47.24) 47.24,-94.49 ; -94.49,47.24 ccw(c47.24,47.24) 47.24,-94.49 ; -94.49,47.24 -94.49,2314.96 ; -94.49,47.24 -94.49,2314.96 ; -94.49,47.24 -94.49,2314.96 ; -94.49,47.24 -94.49,2314.96 ; -94.49,2314.96 cw(c47.24,2314.96) 47.24,2456.69 ; -94.49,2314.96 cw(c47.24,2314.96) 47.24,2456.69 ; -94.49,2314.96 cw(c47.24,2314.96) 47.24,2456.69 ; -94.49,2314.96 cw(c47.24,2314.96) 47.24,2456.69 ; 0,47.24 ccw(c47.24,47.24) 47.24,0 ; 0,47.24 ccw(c47.24,47.24) 47.24,0 ; 0,47.24 ccw(c47.24,47.24) 47.24,0 ; 0,47.24 ccw(c47.24,47.24) 47.24,0 ; 0,47.24 0,2314.96 ; 0,47.24 0,2314.96 ; 0,47.24 0,2314.96 ; 0,47.24 0,2314.96 ; 0,2314.96 cw(c47.24,2314.96) 47.24,2362.2 ; 0,2314.96 cw(c47.24,2314.96) 47.24,2362.2 ; 0,2314.96 cw(c47.24,2314.96) 47.24,2362.2 ; 0,2314.96 cw(c47.24,2314.96) 47.24,2362.2 ; 47.24,-94.49 334.65,-94.49 ; 47.24,-94.49 334.65,-94.49 ; 47.24,-94.49 334.65,-94.49 ; 47.24,-94.49 334.65,-94.49 ; 47.24,0 4480.32,0 ; 47.24,0 4480.32,0 ; 47.24,0 4480.32,0 ; 47.24,0 4480.32,0 ; 47.24,2362.2 4480.32,2362.2 ; 47.24,2362.2 4480.32,2362.2 ; 47.24,2362.2 4480.32,2362.2 ; 47.24,2362.2 4480.32,2362.2 ; 47.24,2456.69 334.65,2456.69 ; 47.24,2456.69 334.65,2456.69 ; 47.24,2456.69 334.65,2456.69 ; 47.24,2456.69 334.65,2456.69 ; 610.24,-94.49 2224.41,-94.49 ; 610.24,-94.49 2224.41,-94.49 ; 610.24,-94.49 2224.41,-94.49 ; 610.24,-94.49 2224.41,-94.49 ; 610.24,2456.69 2224.41,2456.69 ; 610.24,2456.69 2224.41,2456.69 ; 610.24,2456.69 2224.41,2456.69 ; 610.24,2456.69 2224.41,2456.69 ; 2500,-94.49 3720.47,-94.49 ; 2500,-94.49 3720.47,-94.49 ; 2500,-94.49 3720.47,-94.49 ; 2500,-94.49 3720.47,-94.49 ; 2500,2456.69 3720.47,2456.69 ; 2500,2456.69 3720.47,2456.69 ; 2500,2456.69 3720.47,2456.69 ; 2500,2456.69 3720.47,2456.69 ; 3996.06,-94.49 4480.32,-94.49 ; 3996.06,-94.49 4480.32,-94.49 ; 3996.06,-94.49 4480.32,-94.49 ; 3996.06,-94.49 4480.32,-94.49 ; 3996.06,2456.69 4480.32,2456.69 ; 3996.06,2456.69 4480.32,2456.69 ; 3996.06,2456.69 4480.32,2456.69 ; 3996.06,2456.69 4480.32,2456.69 ; 4480.32,-94.49 ccw(c4480.32,47.24) 4622.05,47.24 ; 4480.32,-94.49 ccw(c4480.32,47.24) 4622.05,47.24 ; 4480.32,-94.49 ccw(c4480.32,47.24) 4622.05,47.24 ; 4480.32,-94.49 ccw(c4480.32,47.24) 4622.05,47.24 ; 4480.32,0 ccw(c4480.32,47.24) 4527.56,47.24 ; 4480.32,0 ccw(c4480.32,47.24) 4527.56,47.24 ; 4480.32,0 ccw(c4480.32,47.24) 4527.56,47.24 ; 4480.32,0 ccw(c4480.32,47.24) 4527.56,47.24 ; 4480.32,2362.2 cw(c4480.32,2314.96) 4527.56,2314.96 ; 4480.32,2362.2 cw(c4480.32,2314.96) 4527.56,2314.96 ; 4480.32,2362.2 cw(c4480.32,2314.96) 4527.56,2314.96 ; 4480.32,2362.2 cw(c4480.32,2314.96) 4527.56,2314.96 ; 4480.32,2456.69 cw(c4480.32,2314.96) 4622.05,2314.96 ; 4480.32,2456.69 cw(c4480.32,2314.96) 4622.05,2314.96 ; 4480.32,2456.69 cw(c4480.32,2314.96) 4622.05,2314.96 ; 4480.32,2456.69 cw(c4480.32,2314.96) 4622.05,2314.96 ; 4527.56,47.24 4527.56,2314.96 ; 4527.56,47.24 4527.56,2314.96 ; 4527.56,47.24 4527.56,2314.96 ; 4527.56,47.24 4527.56,2314.96 ; 4622.05,47.24 4622.05,2314.96 ; 4622.05,47.24 4622.05,2314.96 ; 4622.05,47.24 4622.05,2314.96 ; 4622.05,47.24 4622.05,2314.96
Top Component Outline:
  circle w4: c610.24,1535.43 r59.06
  circle w4: c4409.45,2244.09 r59.06
  circle w4: c4409.45,2244.09 r98.43
  lines w3.94: 4394.45,2244.09 4424.45,2244.09 ; 4409.45,2229.09 4409.45,2259.09
Top Courtyard:
  circle w1.97: c610.24,1535.43 r118.11
  circle w1.97: c4409.45,2244.09 r108.27
Top Component Center (Mech19):
  lines w1.97: 4389.76,2244.09 4429.13,2244.09 ; 4409.45,2224.41 4409.45,2263.78
Assembly Drawing Frame (Top):
  lines w7.87: -3324.13,-1427.68 -3260.16,-1427.68 ; -3324.13,409.92 -3260.16,409.92 ; -3324.13,2247.52 -3260.16,2247.52 ; -1172.56,-3327.28 -1172.56,-3264.29 ; -1172.56,4086.1 -1172.56,4149.09 ; 915.04,-3327.28 915.04,-3264.29 ; 915.04,4086.1 915.04,4149.09 ; 3002.64,-3327.28 3002.64,-3264.29 ; 3002.64,4086.1 3002.64,4149.09 ; 5090.24,-3327.28 5090.24,-3264.29 ; 5090.24,4086.1 5090.24,4149.09 ; 7177.83,-1426.69 7241.81,-1426.69 ; 7177.83,410.91 7241.81,410.91 ; 7177.83,2248.5 7241.81,2248.5 ; 7241.81,-3327.28 -3324.13,-3327.28 -3324.13,4149.09 7241.81,4149.09 7241.81,-3326.3 ; -3260.16,-3264.29 -3260.16,4086.1 7177.83,4086.1 7177.83,-3264.29 -3260.16,-3264.29
  text "5" at -2222.76,4106.77 h19.68
  text "4" at -135.16,4105.79 h19.68
  text "3" at 1952.44,4105.79 h19.68
  text "2" at 4040.04,4105.79 h19.68
  text "1" at 6131.57,4105.79 h19.68
  text "D" at 7204.41,3156.97 h19.68
  text "D" at -3297.56,3155.98 h19.68
  text "C" at 7204.41,1318.39 h19.68
  text "C" at -3297.56,1317.4 h19.68
  text "B" at 7204.41,-519.21 h19.68
  text "B" at -3297.56,-520.2 h19.68
  text "A" at 7204.41,-2355.83 h19.68
  text "A" at -3297.56,-2356.81 h19.68
  text "5" at -2222.76,-3306.61 h19.68
  text "4" at -135.16,-3307.6 h19.68
  text "3" at 1952.44,-3307.6 h19.68
  text "2" at 4040.04,-3307.6 h19.68
  text "1" at 6131.57,-3307.6 h19.68
Title Block (Top):
  drawing of 27 lines, arcs and shapes, not listed
  text "Board Title" at 4437.69,-2282.02 h98.43
  text "EFM32 Leopard Gecko Starter Kit" at 4492.81,-2500.53 h137.8
  text "Page Title" at 4437.69,-2664.9 h98.43
  text "Designed:" at 3168.01,-2812.53 h66.93
  text "Approved:" at 3805.8,-2812.53 h66.93
  text "Top Assembly" at 4492.81,-2818.44 h125.98
  text "YVB" at 3228.04,-2910.96 h86.61
  text "MAH" at 3859.93,-2910.96 h86.61
  text "Revision" at 6717.22,-2941.47 h66.93
  text "Document number" at 4437.69,-2952.3 h92.52
  text "Size" at 3168.01,-2999.54 h66.93
  text "Sheet Modified Date" at 3361.9,-2999.54 h66.93
  text "A00" at 6728.04,-3061.55 h106.3
  text "BRD2201B (PCB2201B Rev A00)" at 4492.81,-3065.49 h125.98
  text "A4" at 3190.64,-3072.38 h78.74
  text "'.Print_Date'" at 3384.54,-3072.38 h78.74
  text "Sheet" at 6717.22,-3164.9 h66.93
  text "COPYRIGHT SILICON LABORATORIES  INC. 2022" at 3350.98,-3204.58 h66.93
  text "CONFIDENTIAL -SUBJECT TO TERMS OF USE" at 4925.07,-3204.58 h66.93
  text "1" at 6764.46,-3241.67 h66.93
  text "of" at 6887.49,-3241.67 h66.93
  text "2" at 6994.78,-3241.67 h66.93
Assembly Drawing Frame (Bottom):
  lines w7.87: -3324.13,-1427.68 -3260.16,-1427.68 ; -3324.13,409.92 -3260.16,409.92 ; -3324.13,2247.52 -3260.16,2247.52 ; -1172.56,-3327.28 -1172.56,-3264.29 ; -1172.56,4086.1 -1172.56,4149.09 ; 915.04,-3327.28 915.04,-3264.29 ; 915.04,4086.1 915.04,4149.09 ; 3002.64,-3327.28 3002.64,-3264.29 ; 3002.64,4086.1 3002.64,4149.09 ; 5090.24,-3327.28 5090.24,-3264.29 ; 5090.24,4086.1 5090.24,4149.09 ; 7177.83,-1426.69 7241.81,-1426.69 ; 7177.83,410.91 7241.81,410.91 ; 7177.83,2248.5 7241.81,2248.5 ; 7241.81,-3327.28 -3324.13,-3327.28 -3324.13,4149.09 7241.81,4149.09 7241.81,-3326.3 ; -3260.16,-3264.29 -3260.16,4086.1 7177.83,4086.1 7177.83,-3264.29 -3260.16,-3264.29
  text "5" at -2209.96,4106.77 h19.68
  text "4" at -122.36,4105.79 h19.68
  text "3" at 1965.24,4105.79 h19.68
  text "2" at 4052.83,4105.79 h19.68
  text "1" at 6138.46,4105.79 h19.68
  text "D" at 7217.2,3156.97 h19.68
  text "D" at -3284.76,3155.98 h19.68
  text "C" at 7217.2,1318.39 h19.68
  text "C" at -3284.76,1317.4 h19.68
  text "B" at 7217.2,-519.21 h19.68
  text "B" at -3284.76,-520.2 h19.68
  text "A" at 7217.2,-2355.83 h19.68
  text "A" at -3284.76,-2356.81 h19.68
  text "5" at -2209.96,-3306.61 h19.68
  text "4" at -122.36,-3307.6 h19.68
  text "3" at 1965.24,-3307.6 h19.68
  text "2" at 4052.83,-3307.6 h19.68
  text "1" at 6138.46,-3307.6 h19.68
Title Block (Bottom):
  drawing of 27 lines, arcs and shapes, not listed
  text "Board Title" at -520,-2282.03 h98.43
  text "EFM32 Leopard Gecko Starter Kit" at -575.11,-2500.53 h137.8
  text "Page Title" at -520,-2664.9 h98.43
  text "Approved:" at 111.89,-2812.54 h66.93
  text "Designed:" at 749.69,-2812.54 h66.93
  text "Bottom Assembly" at -575.11,-2818.44 h125.98
  text "MAH" at 57.76,-2910.96 h86.61
  text "YVB" at 689.65,-2910.96 h86.61
  text "Revision" at -2799.52,-2941.48 h66.93
  text "Document number" at -520,-2952.3 h92.52
  text "Sheet Modified Date" at 555.79,-2999.55 h66.93
  text "Size" at 749.69,-2999.55 h66.93
  text "A00" at -2809.92,-3061.55 h106.3
  text "BRD2201B (PCB2201B Rev A00)" at -575.11,-3065.49 h125.98
  text "'.Print_Date'" at 533.15,-3072.38 h78.74
  text "A4" at 727.05,-3072.38 h78.74
  text "Sheet" at -2799.52,-3164.9 h66.93
  text "COPYRIGHT SILICON LABORATORIES  INC. 2022" at 562.23,-3201.75 h66.93
  text "CONFIDENTIAL -SUBJECT TO TERMS OF USE" at -1034.78,-3205.22 h66.93
  text "2" at -3077.08,-3241.67 h66.93
  text "of" at -2969.8,-3241.67 h66.93
  text "2" at -2846.77,-3241.67 h66.93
